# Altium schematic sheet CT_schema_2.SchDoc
size 182 x 229 mm
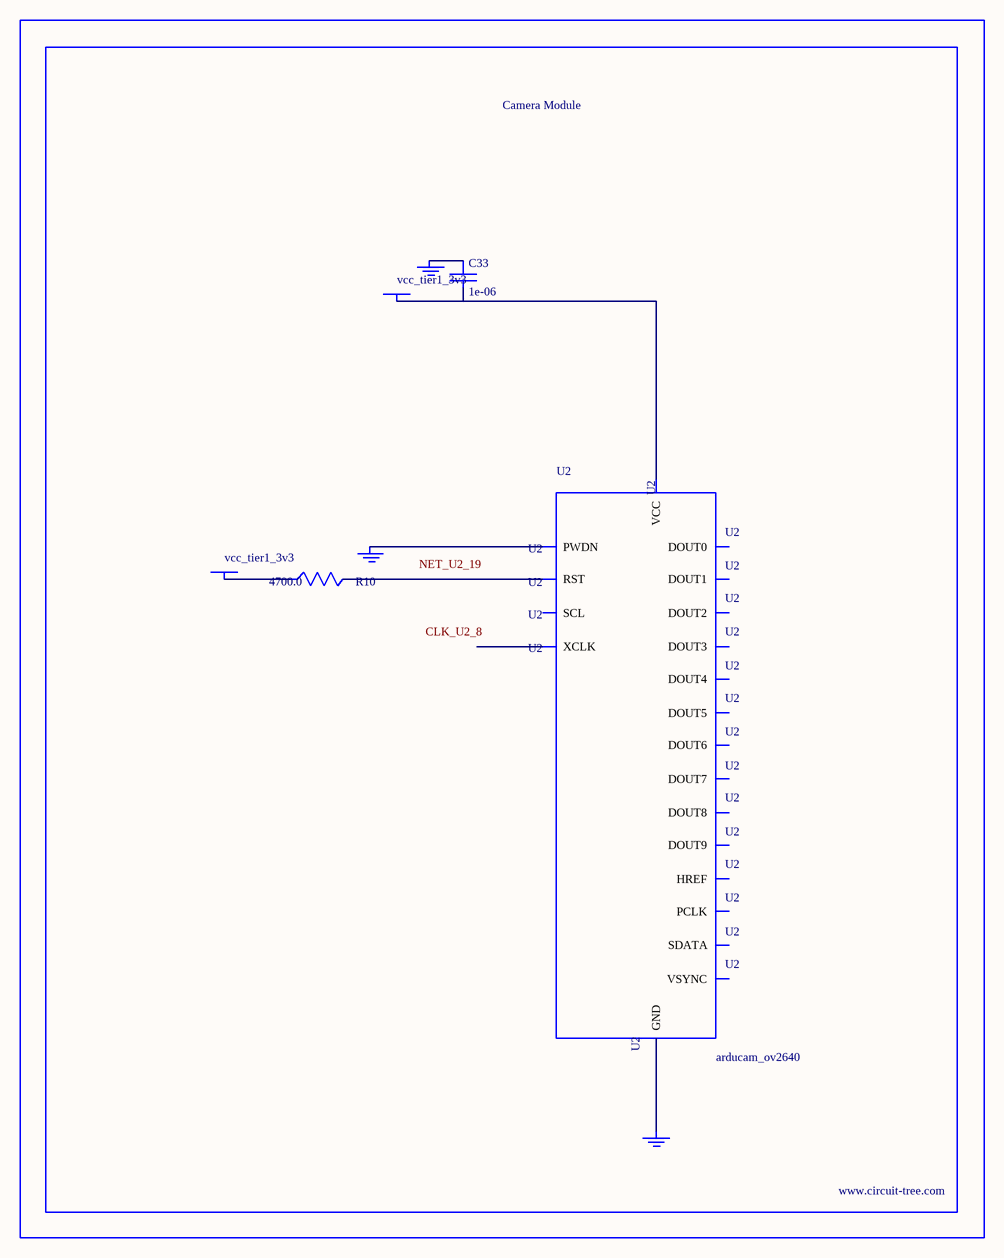
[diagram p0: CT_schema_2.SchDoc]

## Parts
BORDER1  (no value)
C33  1e-06  [C0603]
GND_INSTANCE_1_0  (no value)
GND_INSTANCE_1_1  (no value)
GND_INSTANCE_1_2  (no value)
POWER_INSTANCE_1_0  vcc_tier1_3v3
POWER_INSTANCE_1_1  vcc_tier1_3v3
R10  4700.0  [R0603]
U2  arducam_ov2640  [ARDUCAM]

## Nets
NetC33_1: C33.1 GND_INSTANCE_1_0.0(GND)
NetC33_2: C33.2 POWER_INSTANCE_1_0.0(PWR) U2.1(VCC)
NetGND_INSTANCE_1_1_0: GND_INSTANCE_1_1.0(GND) U2.20(PWDN)
NetGND_INSTANCE_1_2_0: GND_INSTANCE_1_2.0(GND) U2.2(GND)
NetPOWER_INSTANCE_1_1_0: POWER_INSTANCE_1_1.0(PWR) R10.1
NetR10_2: R10.2 U2.19(RST)

Not connected (* = marked no-connect by the designer): U2 3(SCL) 4(SDATA) 5(VSYNC) 6(HREF) 7(PCLK) 8(XCLK) 9(DOUT9) 10(DOUT8) 11(DOUT7) 12(DOUT6) 13(DOUT5) 14(DOUT4) 15(DOUT3) 16(DOUT2) 17(DOUT1) 18(DOUT0)

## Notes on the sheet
- Labels drawn without touching a wire or pin: CLK_U2_8, NET_U2_19

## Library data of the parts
BORDER1 = BORDER_PAGE1
C33 = C0603C105K3RACTU
GND_INSTANCE_1_0-GND_INSTANCE_1_2 = GND
POWER_INSTANCE_1_0 POWER_INSTANCE_1_1 = PWR
R10 = RC0603JR-074K7L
